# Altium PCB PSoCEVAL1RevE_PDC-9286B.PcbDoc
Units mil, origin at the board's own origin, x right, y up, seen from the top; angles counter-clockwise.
Board outline 3000 x 4000 mil, 2 copper layers (Top Layer, Bottom Layer); 58 components, 63 nets, 401 pads, 21 vias.
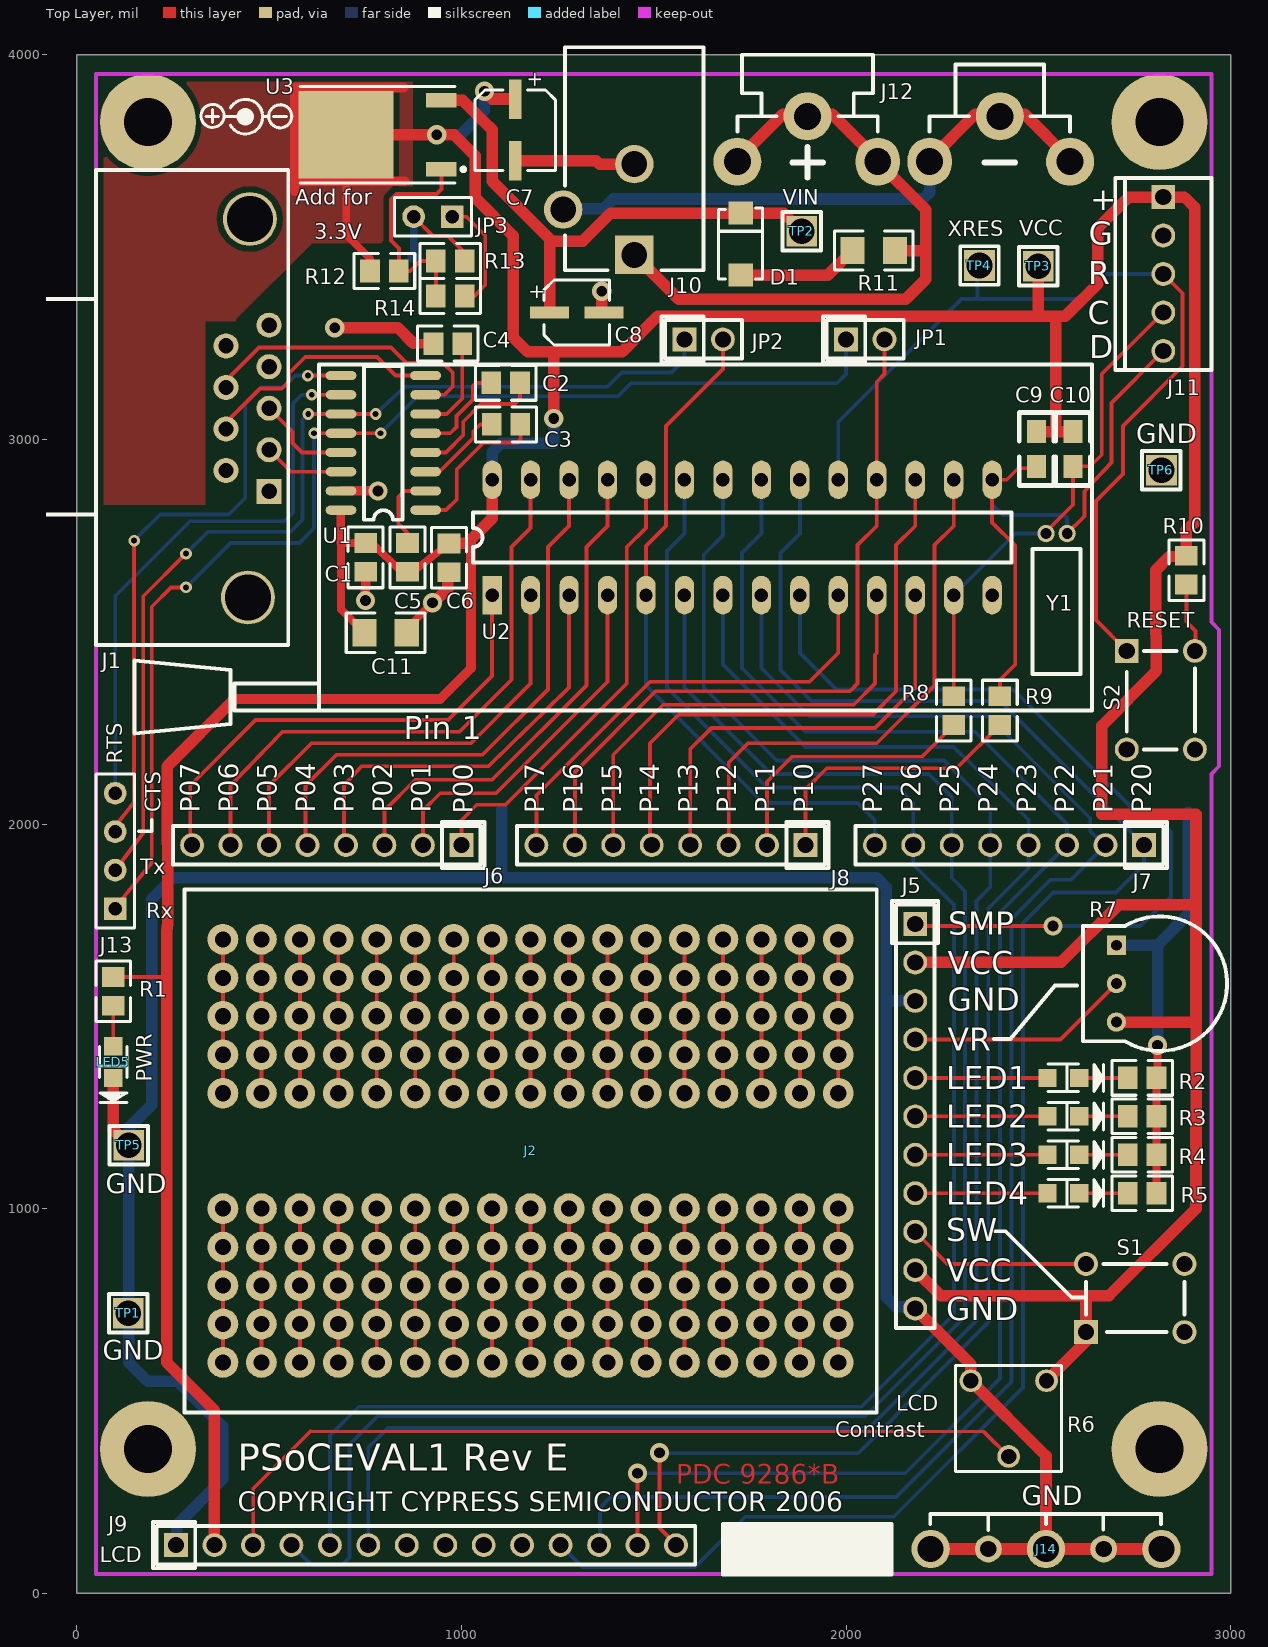
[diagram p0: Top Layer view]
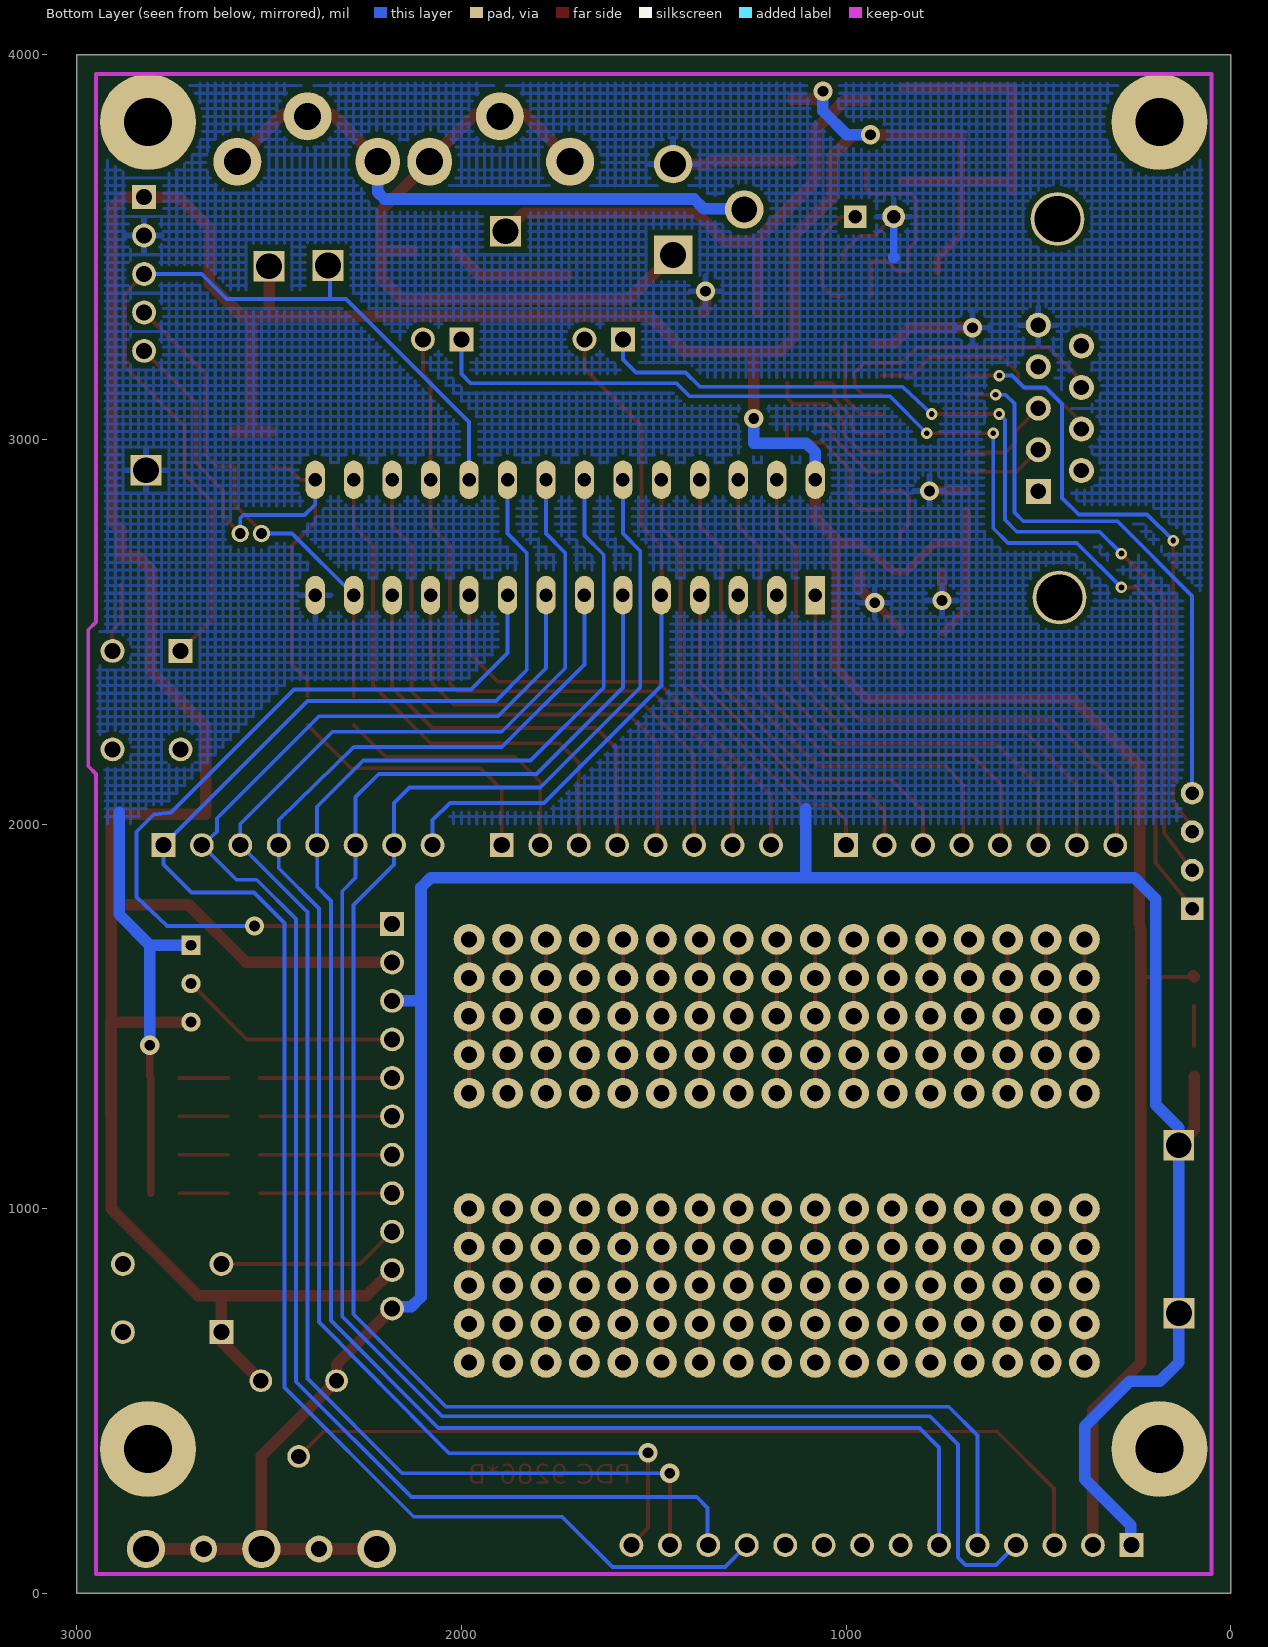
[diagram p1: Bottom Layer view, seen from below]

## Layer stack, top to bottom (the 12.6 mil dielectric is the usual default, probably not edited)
Top Layer: signal copper 1.4
Dielectric: dielectric 12.6, FR-4, Dk 4.8
Bottom Layer: signal copper 1.4

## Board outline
0,0 3000,0 3000,4000 0,4000

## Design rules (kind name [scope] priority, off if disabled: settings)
Clearance Clearance_1 [All vs InPoly] p1: gap=15
Clearance [All] p2: gap=8
ComponentClearance [All] p1: gap=10 collisioncheckmode=0 verticalgap=10
HoleSize [All] p1: absolutevalues=TRUE maxlimit=150 minlimit=15 maxpercent=80.000 minpercent=20.000
PolygonConnect [All] p1: connectstyle=Relief reliefconductorwidth=15 reliefentries=4 polygonreliefangle="90 Angle"
RoutingVias [All] p1: holewidth=25 width=40 viastyle="Through Hole" minholewidth=28 minwidth=50 maxholewidth=28 maxwidth=50
SolderMaskExpansion [All] p1: expansion=4
TestPointUsage [All] p1: valid=0 allowmultiple=FALSE
Testpoint [All] p1: side=15 testpointundercomponent=TRUE minsize=40 maxsize=100 preferedsize=60 minholesize=0 maxholesize=40 preferedholesize=32 testpointgrid=1 style=1023 order=0-112345678
Width [InNetClass('Power')] p1: maxlimit=100 minlimit=8 preferedwidth=10
17 further rules are at their usual default settings.

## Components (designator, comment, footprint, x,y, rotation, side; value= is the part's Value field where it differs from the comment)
C1 "" 0805#1 751,2693 r270 top
C2 "" 0805#1 1115,3147 r180 top
C3 "" 0805#1 1116,3039 r180 top
C4 "" 0805#1 965,3249 r0 top
C5 "" 0805#1 860,2693 r270 top
C6 "" 0805#1 968,2692 r270 top
C7 "" CAP_Nich_WT5.0 1140,3804 r270 top
C8 "" CAP_Nich_WT4-4.5 1300,3330 r0 top
C9 "DNP" 0805#2 2495,2930 r90 top
C10 "DNP" 0805#2 2590,2930 r90 top
C11 "10u" 1206 803,2497 r0 top
D1 "" SMA-A 1726,3427 r270 top
J1 "" DB9F 500,2865 r90 top
J2 "" BBOARD_1.8X1.4 1980,1700 r180 top
J5 "" HDR11X1 2180,1740 r270 top
J6 "" HDR8X1 1000,1945 r180 top
J7 "" HDR8X1 2775,1945 r180 top
J8 "" HDR8X1 1895,1945 r180 top
J9 "" HDR14X1 258,125 r0 top
J10 "" PWRCON 1450,3480 r90 top
J11 "" ISPCON 2825,3630 r270 top
J12 "" 9VBAT 1900,3840 r0 top
J13 "" HDR1X4 100,1780 r90 top
J14 "DNP" HDR5X1-GND 2820,115 r180 top
JP1 "DNP" HDR2x1 2000,3260 r0 top
JP2 "DNP" HDR2x1 1580,3260 r0 top
JP3 "" HDR1X2 976,3579 r180 top
LED1 "" LED0805 2565,1340 r0 top
LED2 "" LED0805 2565,1240 r0 top
LED3 "" LED0805 2565,1140 r0 top
LED4 "" LED0805 2565,1040 r0 top
LED5 "" LED0805 95,1381 r270 top
R1 "" R2012-0805 95,1565 r90 top
R2 "" R2012-0805 2770,1340 r180 top
R3 "" R2012-0805 2770,1240 r180 top
R4 "" R2012-0805 2770,1140 r180 top
R5 "" R2012-0805 2770,1040 r180 top
R6 "" POT_EVND8A 2423,454 r180 top
R7 "" POT-3352T 2703,1685 r270 top
R8 "" R2012-0805 2280,2295 r90 top
R9 "" R2012-0805 2400,2295 r90 top
R10 "" R2012-0805 2885,2660 r90 top
R11 "" 1206 2072,3491 r180 top
R12 "" R2012-0805 800,3438 r180 top
R13 "" R2012-0805 971,3464 r180 top
R14 "" R2012-0805 971,3373 r180 top
S1 "" STDSW 2624,679 r0 top
S2 "" STDSW 2730,2450 r270 top
TP1 "" TP64 134,728 r0 top
TP2 "DNP" TP64 1885,3541 r90 top
TP3 "DNP" TP64 2500,3450 r90 top
TP4 "DNP" TP64 2347,3452 r90 top
TP5 "" TP64 135,1165 r0 top
TP6 "" TP64 2820,2920 r90 top
U1 "" SO-16 907,2816 r180 top
U2 "" DIP-28-ZIF 1080,2595 r90 top
U3 "ADJ Vreg" KTP02 824,3792 r90 top
Y1 "DNP" XTAL32K 2525,2755 r90 top

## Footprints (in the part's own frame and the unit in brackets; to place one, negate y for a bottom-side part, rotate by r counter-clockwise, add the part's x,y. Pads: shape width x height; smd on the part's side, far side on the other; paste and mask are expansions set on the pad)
9VBAT [mil]
  round 125 hole 70: 1(-182.5,-118) 1(0,0) 2(500,0) 2(682.5,-118)
  oval 115x125 hole 70: 1(182.5,-118) 2(317.5,-118)
  silkscreen extent -182,-160 682,160
0805#1 [mm]
  rect 1.3x1.5 smd: 1(-0.95,0) 2(0.95,0)
  silkscreen extent -2,-1.15 2,1.15
0805#2 [mm]
  rect 1.524x1.27 smd: 1(0,0) 2(2.286,0)
  silkscreen extent -1.27,-1.14 3.56,1.14
1206 [mm]
  rect 1.6x1.8 smd: 1(-1.4,0) 2(1.4,0)
  silkscreen extent -2.6,-1.3 2.6,1.3
BBOARD_1.8X1.4 [mil] "28 tie point Breadboard  ( 3M 923273-I )"
  round 80 hole 42: ""(0,1100) ""(0,1000) ""(0,900) ""(0,800) ""(0,700) ""(0,400) ""(0,300) ""(0,200) ""(0,100) ""(0,0) ""(100,1000) ""(100,1100) ""(100,900) ""(100,800) ""(100,700) ""(100,300) ""(100,400) ""(100,200) ""(100,100) ""(100,0) ""(200,1100) ""(200,900) ""(200,1000) ""(200,700) ""(200,800) ""(200,400) ""(200,200) ""(200,300) ""(200,0) ""(200,100) ""(300,700) ""(300,800) ""(300,900) ""(300,1000) ""(300,1100) ""(300,300) ""(300,400) ""(300,0) ""(300,100) ""(300,200) ""(400,700) ""(400,800) ""(400,900) ""(400,1000) ""(400,1100) ""(400,300) ""(400,400) ""(400,0) ""(400,100) ""(400,200) ""(500,700) ""(500,800) ""(500,900) ""(500,1000) ""(500,1100) ""(500,300) ""(500,400) ""(500,0) ""(500,100) ""(500,200) ""(600,700) ""(600,800) ""(600,900) ""(600,1000) ""(600,1100) ""(600,0) ""(600,100) ""(600,200) ""(600,300) ""(600,400) ""(700,700) ""(700,800) ""(700,900) ""(700,1000) ""(700,1100) ""(700,0) ""(700,100) ""(700,200) ""(700,300) ""(700,400) ""(800,700) ""(800,800) ""(800,900) ""(800,1000) ""(800,1100) ""(800,0) ""(800,100) ""(800,200) ""(800,300) ""(800,400) ""(900,700) ""(900,800) ""(900,900) ""(900,1000) ""(900,1100) ""(900,0) ""(900,100) ""(900,200) ""(900,300) ""(900,400) ""(1000,700) ""(1000,800) ""(1000,900) ""(1000,1000) ""(1000,1100) ""(1000,0) ""(1000,100) ""(1000,200) ""(1000,300) ""(1000,400) ""(1100,1000) ""(1100,1100) ""(1100,0) ""(1100,100) ""(1100,200) ""(1100,300) ""(1100,400) ""(1100,700) ""(1100,800) ""(1100,900) ""(1200,1000) ""(1200,1100) ""(1200,0) ""(1200,100) ""(1200,200) ""(1200,300) ""(1200,400) ""(1200,700) ""(1200,800) ""(1200,900) ""(1300,1000) ""(1300,1100) ""(1300,0) ""(1300,100) ""(1300,200) ""(1300,300) ""(1300,400) ""(1300,700) ""(1300,800) ""(1300,900) ""(1400,1000) ""(1400,1100) ""(1400,0) ""(1400,100) ""(1400,200) ""(1400,300) ""(1400,400) ""(1400,700) ""(1400,800) ""(1400,900) ""(1500,1000) ""(1500,1100) ""(1500,0) ""(1500,100) ""(1500,200) ""(1500,300) ""(1500,400) ""(1500,700) ""(1500,800) ""(1500,900) ""(1600,1000) ""(1600,1100) ""(1600,0) ""(1600,100) ""(1600,200) ""(1600,300) ""(1600,400) ""(1600,700) ""(1600,800) ""(1600,900)
  Top Layer lines w10: 1600,1100 1600,700 ; 1600,400 1600,0 ; 1500,1100 1500,700 ; 1500,400 1500,0 ; 1400,1100 1400,700 ; 1400,400 1400,0 ; 1300,1100 1300,700 ; 1300,400 1300,0 ; 1200,1100 1200,700 ; 1200,400 1200,0 ; 1100,1100 1100,700 ; 1100,400 1100,0 ; 1000,1100 1000,700 ; 1000,400 1000,0 ; 900,1100 900,700 ; 900,400 900,0 ; 800,1100 800,700 ; 800,400 800,0 ; 700,1100 700,700 ; 700,400 700,0 ; 600,1100 600,700 ; 600,400 600,0 ; 500,1100 500,700 ; 500,400 500,0 ; 400,1100 400,700 ; 400,400 400,0 ; 300,1100 300,700 ; 300,400 300,0 ; 200,1100 200,700 ; 200,400 200,0 ; 100,1100 100,700 ; 100,400 100,0 ; 0,1100 0,700 ; 0,400 0,0
  silkscreen extent -100,-130 1700,1230
CAP_Nich_WT4-4.5 [mm]
  rect 2.6x0.8 smd: 1(-1.8,0) 2(1.8,0)
  silkscreen extent -2.15,-2.15 2.15,2.15
CAP_Nich_WT5.0 [mm]
  rect 2.6x0.8 smd: 1(-2.032,0) 2(2.032,0)
  silkscreen extent -2.65,-2.65 2.65,2.65
DB9F [mil]
  rect 65x65 hole 40: 1(0,0)
  round 65 hole 40: 2(108,0) 3(216,0) 4(324,0) 5(432,0) 6(54,112) 7(162,112) 8(270,112) 9(378,112)
  round 140 hole 120: ""(-276,55) ""(708,50)
  silkscreen extent -400,-50 835,600
DIP-28-ZIF [mil]
  rect 100x50 hole 35: 1(0,0)
  oval 100x50 hole 35: 2(0,-100) 3(0,-200) 4(0,-300) 5(0,-400) 6(0,-500) 7(0,-600) 8(0,-700) 9(0,-800) 10(0,-900) 11(0,-1000) 12(0,-1100) 13(0,-1200) 14(0,-1300) 15(300,-1300) 16(300,-1200) 17(300,-1100) 18(300,-1000) 19(300,-900) 20(300,-800) 21(300,-700) 22(300,-600) 23(300,-500) 24(300,-400) 25(300,-300) 26(300,-200) 27(300,-100) 28(300,0)
  silkscreen extent -360,-1560 600,930
HDR1X2 [mm] "Connector; Header; 2 Position"
  rect 1.5x1.5 hole 0.9: 1(0,0)
  round 1.5 hole 0.9: 2(2.54,0)
  silkscreen extent -1.27,-1.27 3.81,1.27
HDR1X4 [mm] "Connector; Header; 4 Position"
  rect 1.5x1.5 hole 0.889: 1(0,0)
  round 1.5 hole 0.889: 2(2.54,0) 3(5.08,0) 4(7.62,0)
  silkscreen extent -1.27,-1.27 8.89,1.27
HDR2x1 [mil]
  rect 62x62 hole 42: 1(0,0)
  round 62 hole 42: 2(100,0)
  silkscreen extent -60,-60 150,60
HDR5X1-GND [mil]
  round 100 hole 67: 1(0,0) 3(300,0) 5(600,0)
  round 70 hole 42: 2(150,0) 4(450,0)
HDR8X1 [mil]
  rect 62x62 hole 42: 1(0.12,-0.12)
  round 62 hole 42: 2(100.12,-0.12) 3(200.12,-0.12) 4(300.12,-0.12) 5(400.12,-0.12) 6(500.12,-0.12) 7(600.12,-0.12) 8(700.12,-0.12)
  silkscreen extent -60,-60 750,60
HDR11X1 [mil]
  rect 62x62 hole 42: 1(0,0)
  round 62 hole 42: 2(100,0) 3(200,0) 4(300,0) 5(400,0) 6(500,0) 7(600,0) 8(700,0) 9(800,0) 10(900,0) 11(1000,0)
  silkscreen extent -60,-60 1050,60
HDR14X1 [mil]
  rect 62x62 hole 42: 1(0,0)
  round 62 hole 42: 2(100,0) 3(200,0) 4(300,0) 5(400,0) 6(500,0) 7(600,0) 8(700,0) 9(800,0) 10(900,0) 11(1000,0) 12(1100,0) 13(1200,0) 14(1300,0)
  silkscreen extent -60,-60 1350,60
ISPCON [mil]
  rect 62x62 hole 42: 1(0,0)
  round 62 hole 42: 2(100,0) 3(200,0) 4(300,0) 5(400,0)
  silkscreen extent -50,-125 450,125
KTP02 [mm] "PowerFLEX (D-PAK/TO-252-AA); 3 Leads (1 Cropped); Body 9.7 (inc. leads) x 6.2 mm (LxW max)"
  rect 0.95x2 smd: 1(-2.285,-3.15) 3(2.285,-3.15)
  rect 5.8x6.3 smd: 4(0,3.15)
  silkscreen extent -3.2,-4.72 3.2,6.2
LED0805 [mm]
  rect 1.2x1.2 smd: A(-1.05,0) K(1.05,0)
  silkscreen extent -1.02,-0.9 2.67,0.9
POT-3352T [mil]
  rect 50x50 hole 28: 1(0,0)
  round 50 hole 28: 2(200,0) 3(100,0)
  silkscreen extent -75,-87 275,288
POT_EVND8A [mm]
  round 1.5 hole 1.016: 1(-2.5,-2.5) 2(2.5,-2.5) 3(0,2.5)
  silkscreen extent -3.5,-3.5 3.5,3.5
PWRCON [mil]
  rect 100x100 hole 67: 1(-0.33,0.33)
  round 100 hole 67: 2(235.67,0.33) 3(117.67,185.33)
  silkscreen extent -40,-180 540,180
R2012-0805 [mm]
  rect 1.3x1.5 smd: 1(-0.95,0) 2(0.95,0)
  silkscreen extent -2,-1.15 2,1.15
SMA-A [mm]
  rect 1.52x1.63 smd: 1(0,0) 2(-4.1,0)
  silkscreen extent -4.44,-1.45 0.25,1.45
SO-16 [mil]
  oval 80x24 smd: 1(0,0) 2(0,-50) 3(0,-100) 4(0,-150) 5(0,-200) 6(0,-250) 7(0,-300) 8(0,-350) 9(220,-350) 10(220,-300) 11(220,-250) 12(220,-200) 13(220,-150) 14(220,-100) 15(220,-50) 16(220,0)
  silkscreen extent 60,-375 160,25
STDSW [mil]
  rect 62x62 hole 42: 1(0,0)
  round 62 hole 42: 2(0,177) ""(256,0) ""(256,177)
  silkscreen extent 0,0 256,177
TP64 [mil]
  rect 80x80 hole 67: 1(0,0)
  silkscreen extent -50,-50 50,50
XTAL32K [mil]
  round 45 hole 28: 1(0,5) 2(0,-50)
  silkscreen extent -365,-85 -40,40

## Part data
C1 C2 C3 C4 C5 C7 C8 C11: library part CAPACITOR, "Capacitor"
C6 C9 C10: library part CAP, "Capacitor"
D1: library part "DIODE SCHOTTKY", "Schottky Diode"
J1: library part DB9, "Female DB-9"
J2: library part BREADBOARD, "3M solderless breadboard super strip"
J5: library part MHDR1X11, "Header, 11-Pin"
J6 J7 J8: library part CON8, "8-Pin Header, Female"
J9: library part LCD_MODULE, "14-Pin header, Female"
J10: library part PWRCON, "Power connector"
J11: library part CON5, "ISSP connector"
J12: library part BAT-9V-CONN, "9-Volt batter connector"
J13: library part "Header 4", "Header, 4-Pin"
J14: library part "Header 5", "Ground conn."
JP1 JP2 JP3: library part "Header 2", "Header, 2-Pin, Male"
LED1 LED2 LED3 LED4: library part LED
LED5: library part LED, "Red LED"
R1 R2 R3 R4 R5 R8 R9 R10 R11 R12 R13 R14: library part RES1, "Resistor, SMT"
R6 R7: library part POT1, "Potentiometer"
S1 S2: library part SPST, "Swtich, SPST"
TP1 TP2 TP3 TP4 TP5 TP6: library part TP, "Simple Test point"
U1: library part MAX232, "RS-232 tranceiver (1.0uF Caps)"
U2: library part CYMICRO_26443A, "CMS 27443, w/ socket"
U3: library part LM317MKTPR, "Adjustable Voltage Regulator"
Y1: library part CRYSTAL, "Crystal"

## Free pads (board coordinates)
  round 50 on Drill Drawing mask+12.01: 0(5550,4915) 0(5550,5215) 0(5550,5815) 0(5550,6265) 0(5550,6565) 0(5550,6865) 0(5550,7165) 0(5550,8265) 0(5800,7465) 0(5800,7765) 0(5800,8065)
  round 250 hole 125 paste+5: ""(185,375) ""(185,3825) ""(2815,375) ""(2815,3825)

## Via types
v1: diameter 30, hole 15, Top Layer to Bottom Layer, tented both sides, 9 vias
v2: diameter 50, hole 28, Top Layer to Bottom Layer, tented both sides, 8 vias
v3: diameter 50, hole 28, Top Layer to Bottom Layer, 4 vias

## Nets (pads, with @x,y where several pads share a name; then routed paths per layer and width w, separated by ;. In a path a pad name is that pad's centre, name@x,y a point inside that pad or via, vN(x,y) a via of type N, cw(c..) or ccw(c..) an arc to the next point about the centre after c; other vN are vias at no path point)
CTS: J13.3 U1.9 | length 1631.2
  Top Layer w10: J13.3 100,1994 149,2056 v1(149,2737) ; v1(601,3166) U1.9
  Bottom Layer w10: v1@150,2738 217,2805 395,2805 438,2848 438,3092 481,3135 537,3135 568,3166 v1(601,3166)
GND: C1.2 C4.1 C6.2 C7.2 C8.2 C11.2 J1.5 J5.3 J5.11 J9.1 J10.2 J11.2 J14.1 J14.2 J14.3 J14.4 J14.5 JP3.2 LED5.K R2.1 R3.1 R4.1 R5.1 R6.2 R7.1 R13.1 TP1.1 TP5.1 TP6.1 U1.15 U2.14 | length 9276.5
  Top Layer w10: 875,3249 875,3250 ; JP3.2 926,3529 965,3529 1008.4,3485.6 R13.1 ; C6.2@963,2649.6 C6.2
  Top Layer w20: C11.2 858.12,2508.12 v2(925,2575) ; R5.1 R4.1 R3.1 R2.1 2810,1342.6 v3(2810,1425)
  Top Layer w25: U1.15 v2(783,2866) ; v2(750.53,2581) C1.2 ; 875,3249 C4.1
  Top Layer w30: LED5.K@95,1343.66 LED5.K 95,1205 TP5.1 ; v3(671,3290) 835,3290 875,3250 ; v2(925,2575) 965,2610 C6.2@963,2649.6 ; C7.2@1140,3725 1350,3725 1360,3715 1449,3715 J10.2 J10.2@1450,3716 ; v2(1365,3385) 1365,3335.87 C8.2 ; J5.11 2324.57,595.43 R6.2 2520,357 J14.3 ; J14.5 J14.4 J14.3 ; 2600,116 2601,115 ; J14.1 J14.2 2601,115 ; J14.3 2601,115
  Bottom Layer w10: 875,3472 876,3473
  Bottom Layer w20: 876,3473 JP3.2
  Bottom Layer w30: J9.1 260,127 260,177 379,296 379,434 262,551 184,551 135,600 135,728 TP5.1 135,1210 195,1270 195,1805 250,1860 2080,1860 2105,1835 2105,770 2130,745 2175,745 J5.11 ; 874.99,3473.89 876,3473.89 ; 1105,1860 1105,2040 ; 2105,1540 J5.3 ; R7.1 2810,1685 ; v3(2810,1425) 2810,1685 ; J11.2@2820,3525 J11.2 ; 2890,2030 2890,1765 2810,1685
NetC2_1: C2.1 U1.4 | length 364.7
  Top Layer w10: U1.4 960,2966 1005,3011 1005,3046 1051,3092 1138,3092 1152.4,3106.4 C2.1
NetC2_2: C2.2 U1.5 | length 262.4
  Top Layer w10: U1.5 971,3016 987,3032 987,3061 1030,3104 1030,3139 1038,3147 C2.2
NetC3_1: C3.1 U1.1 | length 407.7
  Top Layer w10: U1.1 960,2816 988,2844 988,2922 1058,2992 1146,2992 1153.4,2999.4 C3.1
NetC3_2: C3.2 U1.3 | length 232.5
  Top Layer w10: U1.3 943,2916 1031,3004 1031,3021 1049,3039 C3.2
NetC4_2: C4.2 U1.6 | length 254.7
  Top Layer w10: U1.6 962,3066 1002.4,3106.4 C4.2
NetC5_1: C5.1 U1.2 | length 207.8
  Top Layer w10: C5.1 860,2757 836,2781 836,2851 851,2866 U1.2
NetC8_1: C8.1 D1.2 TP2.1 U3.3 | length 1406.4
  Top Layer w10: 1230,3515 1230,3521
  Top Layer w30: U3.3 1003.04,3881.96 1059,3826 1080,3805 1080,3671 1230,3521 ; C8.1 1230,3330.87 1230,3515 1315,3515 1388.42,3588.42 D1.2 1837.58,3588.42 TP2.1
NetD1_1: D1.1 R11.2 | length 317.4
  Top Layer w30: D1.1 1952.88,3427 R11.2
NetJ1_2: J1.2 U1.14 | length 210.6
  Top Layer w10: J1.2 557,2916 U1.14
NetJ1_3: J1.3 U1.13 | length 251.6
  Top Layer w10: J1.3 561,3020 561,2991 586,2966 U1.13
NetJ1_7: J1.7 U1.8 | length 638
  Top Layer w10: J1.7 388,3044 476,3132 533,3132 552,3151 552,3172 595,3215 ; 596,3214 781,3214 829,3166 U1.8
NetJ1_8: J1.8 U1.7 | length 785.6
  Top Layer w10: J1.8 388,3153 474,3239 817,3239 857,3199 952,3199 977.4,3173.6 977.4,3137.4 956,3116 U1.7
NetJ5_4: J5.4 R7.3 | length 583.1
  Top Layer w10: J5.4 2558,1440 R7.3
NetJ5_5: J5.5 LED1.A | length 343.7
  Top Layer w10: J5.5 LED1.A
NetJ5_6: J5.6 LED2.A | length 343.7
  Top Layer w10: J5.6 LED2.A
NetJ5_7: J5.7 LED3.A | length 343.7
  Top Layer w10: J5.7 LED3.A
NetJ5_8: J5.8 LED4.A | length 343.7
  Top Layer w10: J5.8 LED4.A
NetJ5_9: J5.9 S1.2 | length 478.8
  Top Layer w10: J5.9 2264,856 S1.2
NetJ9_3: J9.3 R6.3 | length 2200.1
  Top Layer w10: J9.3 459,126 459,272 608,421 2359,420.02 2359,419.57 R6.3
NetJ10_1: J10.1 J12.1 R11.1 | length 1727.9
  Top Layer w30: J10.1@1429.67,3479.67 J10.1@1430,3479.34 ; J10.1 1565.34,3364 2155,3364 2207,3416 2207,3490 ; J12.1@1717.5,3727 1835.5,3845 1900,3845 1964.5,3845 J12.1@2082.5,3727 ; J12.1@2082.5,3722 2207,3597.5 2207,3490 ; R11.1 2128.12,3490 2207,3490
NetJ10_3: J10.3 J12.2 | length 1514.2
  Top Layer w30: J12.2@2217.5,3727 2335.5,3845 2400,3845 2464.5,3845 2582.5,3727 J12.2@2582.5,3727.5
  Bottom Layer w10: J10.3 J10.3@1267,3600
  Bottom Layer w30: J10.3@1267,3600 1370,3600 1395,3625 2200,3625 2217.5,3642.5 J12.2@2217.5,3722
NetJP3_1: JP3.1 R14.1 | length 300.5
  Top Layer w10: JP3.1 1013,3579 1062,3530 1062,3401 1034,3373 R14.1
NetLED1_K: LED1.K R2.2 | length 126.3
  Top Layer w10: LED1.K R2.2
NetLED2_K: LED2.K R3.2 | length 126.3
  Top Layer w10: LED2.K R3.2
NetLED3_K: LED3.K R4.2 | length 126.3
  Top Layer w10: LED3.K R4.2
NetLED4_K: LED4.K R5.2 | length 126.3
  Top Layer w10: LED4.K R5.2
NetLED5_A: LED5.A R1.1 | length 105.3
  Top Layer w10: LED5.A R1.1
NetR10_1: R10.1 S2.2 | length 182.6
  Top Layer w10: R10.1 2885,2526 2909,2502 S2.2
NetR12_1: R12.1 R13.2 R14.2 U3.1 | length 585.6
  Top Layer w10: R14.2 R13.2 893,3464 867,3438 R12.1 837.4,3496.6 817,3517 817,3624 831,3638 935,3638 948.02,3651.02 U3.1
P00: J6.1 U2.24 | length 1192.7
  Top Layer w10: J6.1 999.88,2009.88 1040,2050 1115,2050 1430,2365 1430,2720 1480,2770 U2.24
P01: J6.2 U2.4 | length 933.7
  Top Layer w10: J6.2 900,1945.24 900,2035 945,2080 1090,2080 1380,2370 1380,2445 U2.4
P02: J6.3 U2.25 | length 1307.3
  Top Layer w10: J6.3 800,2035 880,2115 1080,2115 1325,2360 1325,2720 1380,2775 U2.25
P03: J6.4 U2.3 | length 1087.6
  Top Layer w10: J6.4 695,1950 695,2100 740,2150 1070,2150 1280,2355 1280,2445 U2.3
P04: J6.5 U2.26 | length 1458.2
  Top Layer w10: J6.5 595,1950 595,2100 675,2180 1055,2180 1225,2350 1225,2720 1280,2775 U2.26
P05: J6.6 U2.2 | length 1174.7
  Top Layer w10: J6.6 500,1945.24 500,2100 610,2210 1025,2210 1180,2365 1180,2445 U2.2
P06: J6.7 U2.27 | length 1541
  Top Layer w10: J6.7 400,2100 535,2240 995,2240 1130,2375 1130,2720 1180,2770 U2.27
P07: J6.8 U2.1 | length 1270
  Top Layer w10: J6.8 295,1950 295,2100 465,2270 965,2270 1080,2385 U2.1
P10: J8.1 R9.1 | length 719.4
  Top Layer w10: J8.1 1894.88,2089.88 1950,2145 2287.4,2145 R9.1
P10A: C9.1 J11.5 R9.2 U2.15 Y1.2 | length 1625
  Top Layer w10: R9.2 2400,2375 2440,2415 2440,2724 2380,2784 U2.15 2418,2895 2448,2925 2490,2925 C9.1 ; Y1.2 2620,2800 2620,2865 2690,2940 2690,3095 J11.5
  Bottom Layer w10: U2.15 2380,2831 2408,2803 2566.01,2803 ; 2566.5,2803.5 2566.01,2803 ; Y1.2 2575,2795 2566.01,2803
P11: J8.2 R8.1 | length 711.1
  Top Layer w10: J8.2 1794.88,2109.88 1860,2175 2197.4,2175 R8.1
P11A: C10.1 J11.4 R8.2 U2.13 Y1.1 | length 1396.5
  Top Layer w10: R8.2 2280,2445 U2.13 ; Y1.1 2520,2760 2590.15,2830.15 ; J11.4 2665,3170 2665,2960 2635,2930 C10.1 ; C10.1 2590.15,2929.85 2590.15,2830.15 ; C10.1 2590.15,2830.15
  Bottom Layer w10: U2.13 2440,2755 Y1.1
P12: J8.3 U2.16 | length 1388.5
  Top Layer w10: J8.3 1695,1945.24 1695,2160 1745,2210 2080,2210 2230,2360 2230,2725 2280,2775 U2.16
P13: J8.4 U2.12 | length 1141.2
  Top Layer w10: J8.4 1595,1945.24 1595,2195 1650,2250 2075,2250 2180,2355 2180,2445 U2.12
P14: J8.5 U2.17 | length 1533.5
  Top Layer w10: J8.5 1490,1950 1490,2210 1565,2285 2070,2285 2130,2345 2130,2725 2180,2775 U2.17
P15: J8.6 U2.11 | length 1223.6
  Top Layer w10: J8.6 1394.88,2179.88 1525,2310 2020,2310 2075,2365 2075,2440 2080,2445 U2.11
P16: J8.7 JP1.2 U2.18 | length 1944.2
  Top Layer w10: J8.7 1295,1945.24 1295,2135 1505,2345 2010,2345 2030,2365 2030,2725 2080,2775 U2.18 2080,3045 2080,3150 2100,3170 JP1.2
P17: J8.8 U2.10 | length 1218.2
  Top Layer w10: J8.8 1194.88,2074.88 1490,2370 1905,2370 1980,2445 U2.10
P20: J7.1 J9.11 U2.20 | length 4704
  Bottom Layer w10: J9.11 1315,68 1607,68 1738,199 2124,199 2460,535 2460,1742.58 2539,1821.58 2701.58,1821.58 2774.88,1894.88 J7.1 ; U2.20 1880,2755 1830,2705 1830,2400 1910,2320 2400,2320 J7.1 ; J7.1@2775,1945.24 J7.1
P21: J7.2 J9.12 U2.8 | length 4125.7
  Bottom Layer w10: J9.12 1360,127 1360,222 1388,250 2130,250 2430,550 2430,1753 2532,1855 2584.76,1855 J7.2 2635,1980 2635,2015 2370,2280 1905,2280 1780,2405 U2.8
P22: J7.3 J9.13 U2.21 | length 4269.7
  Top Layer w10: J9.13 v2(1458,312)
  Bottom Layer w10: v2(1458,312) 2154,312 2400,558 2400,1772 2401.76,1772 J7.3 ; U2.21 1780,2755 1730,2705 1730,2405 1895,2240 2335,2240 2575,2000 J7.3@2575,1945.24
P23: J7.4 J9.14 U2.7 | length 3744
  Top Layer w10: v2(1515,365) 1515,170 J9.14
  Bottom Layer w10: v2(1515,365) 2032,364 2051,383 2370.05,705.05 ; U2.7 1680,2415 1895,2200 2280,2200 2475,2010 J7.4@2475,1945.24 ; 2370,705.11 2370,1780 2474.88,1884.88 J7.4
P24: J7.5 J9.6 U2.22 | length 4756.5
  Bottom Layer w10: J9.6 758,379 809,430 2060,430 2339.12,709.12 2339.12,1800 2374.88,1835.76 J7.5 ; U2.22 1680,2750 1630,2700 1630,2355 1820,2165 2255,2165 2375,2045 J7.5@2375,1945.24
P25: J7.6 J9.4 U2.6 | length 4631.1
  Bottom Layer w10: J9.4 610,73 689,73 709,93 709,387 782,460 2050,460 2309.76,719.76 2309.76,1825.24 2274.88,1860.12 J7.6 2274.88,2070.12 2215,2130 1805,2130 1580,2355 U2.6
P26: J7.7 J9.5 U2.23 | length 4734.5
  Bottom Layer w10: J9.5 658,410 733,485 2040,485 2280.49,725.49 2280.49,1789.51 2175,1895 2175,1945.12 J7.7@2175,1945.24 ; U2.23 1580,2755 1535,2710 1535,2355 1795,2095 2135,2095 2175,2055 J7.7@2175,1945.24 ; J7.7 J7.7@2175,1945.24
P27: J7.8 JP2.2 U2.5 | length 1787.8
  Top Layer w10: U2.5 1480,2723 1532,2775 1532,3035 1680,3183 JP2.2
  Bottom Layer w10: U2.5 1480,2360 1785,2055 2030,2055 2074.88,2010.12 J7.8 J7.8@2075,1945.24
RTS: J13.4 U1.10 | length 1482.4
  Top Layer w10: v1(611,3116) U1.10
  Bottom Layer w10: J13.4 100,2593 294,2787 539,2787 562,2810 562,3093 585,3116 v1(611,3116)
RX: J13.1 JP1.1 U1.12 | length 3116.8
  Top Layer w10: J13.1@93,1775 98.28,1781.42 195,1899 195,2565 245,2615 v1(284,2615) ; v1(617,3016) v1(790,3016)
  Bottom Layer w10: v1(284,2615) 400,2731 579,2731 617,2769 v1(617,3016) ; v1(790,3016) 886,3112 1407,3112 1441,3146 1976,3146 2000,3170 JP1.1
SMP: J5.1 U2.9 | length 2172.5
  Top Layer w10: J5.1 2185,1735 v2(2538,1735)
  Bottom Layer w10: U2.9 1880,2445 1975,2350 2435,2350 2755,2030 2800,2025 2845,1980 2845,1810 2765,1735 v2(2538,1735)
TX: J13.2 JP2.1 U1.11 | length 2612
  Top Layer w10: J13.2 173,1977 173,2592 v1(284,2703) ; v1(602,3066) v1(777,3066)
  Bottom Layer w10: v1(284,2703) 341,2760 556,2760 587,2791 587,3051 v1(602,3066) ; v1@786.4,3069.4 783,3066 v1(777,3066) 854,3137 1380,3137 1417,3174 1546,3174 1580,3208 JP2.1
VCC: C1.1 C5.2 C6.1 C7.1 C9.2 C10.2 C11.1 J5.2 J5.10 J9.2 J11.1 R1.2 R6.1 R7.2 R10.2 R12.2 S1.1 TP3.1 U1.16 U2.28 U3.4 | length 14993.3
  Top Layer w10: R1.2 233.6,1602.4 234,1602 ; U3.4 U3.4@700.4,3791.58 ; 852,3671 853,3672
  Top Layer w20: U3.4@700.4,3791.58 700.4,3531.6 762.6,3469.4 R12.2 ; C11.1 687,2557.88 687,2585.47 U1.16 685,2805 685,2730 717.6,2730.4 768.6,2730.4 843.4,2655.6 872.6,2655.6 C6.1
  Top Layer w25: 410,2325 770,2325 945,2325 1025,2405 1025,2744 ; 567,3645 567,3915 850,3915 ; 567,3671 852,3671
  Top Layer w30: R1.2 R1.2@97.6,1605 ; J9.2 358,476 234,600 234,1722 237,1741 235,2150 410,2325 ; U3.4 981,3792 1036,3737 1036,3628 1135,3529 1135,3265 1172,3228 1418,3228 1510,3320 2570,3320 2655,3405 2655,3550 2735,3630 J11.1 2880,3630 2907,3603 2907,2784 2885,2765 R10.2 2840,2695 2805,2660 2805,2585 2807,2398 2665,2255 2665,2025 2910,2025 2910,1485 R7.2 ; C6.1 1014.4,2729.4 1080,2795 U2.28 U2.28@1077.6,2897.4 ; v2(1060,3905) 1080,3885 C7.1@1140,3885 ; v3@1240,3048 1240,3228 ; J5.10 2246,774 2685,774 ; J5.2 2560,1641 2709,1790 2910,1790 ; C9.2 C10.2 ; 2500,3320 TP3.1 ; R6.1 2624,655 S1.1 2624,774 ; 2545,3020 2545,3320 ; 2684,774 2910,1000 2911,1484
  Bottom Layer w30: v3(936,3792) 998,3792 1060,3854 v2(1060,3905) ; U2.28 1080,2967 1103,2990 1240,2990 v3@1240,3052.95
  other v3: 1240,3054
XRES: J11.3 S2.1 TP4.1 U2.19 | length 2370.6
  Top Layer w10: S2.1 2650,2530 2650,2840 2720,2910 2720,3035 2875,3190 2875,3380 J11.3
  Bottom Layer w10: U2.19 1980,3045 2300,3365 2610,3365 2675,3430 J11.3 ; 2342,3365 2342,3447 TP4.1
pads on no net: J1. J1.1 J1.4 J1.6 J1.9 J2. J9.7 J9.8 J9.9 J9.10 S1. S2.

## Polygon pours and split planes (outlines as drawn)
VCC on Top Layer "Top Layer-VCC" (solid, remove dead copper, pour order 1000): 53,3954 873,3954 873,3510 609,3510 609,3508 413,3312 413,3307 334,3307 334,2830 49,2830 49,3954
GND on Bottom Layer "Bottom Layer-GND" (hatched 90Degree grid 20 track 8, remove dead copper, pour order 1001): 44,3956 2947,3956 2947,2000 49,2000 49,3956
no net on Top Overlay (hatched Horizontal grid 8 track 10, remove dead copper): 1680,180 2119,180 2119,49 1680,49

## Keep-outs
Keep-Out Layer:
  lines w10: 50,50 2950,50 2950,2130 2970,2150 2970,2505 2950,2525 2950,3950 50,3950 50,50

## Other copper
Top Layer:
  text "TOP COPPER (.GTL)" at 5478,1246 h80
  text "PDC 9286*B" at 1558,285 h50
Bottom Layer:
  text "BOTTOM COPPER (.GBL)" at 5473,1081 h80

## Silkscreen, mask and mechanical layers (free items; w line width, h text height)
Top Overlay:
  circle w25: c438.11,3839 r10
  circle w8: c353,3841 r30
  circle w8: c529,3840 r30
  lines w8: 336,3840 369,3840 ; 353,3824 353,3857 ; 384,3839 421,3839 ; 399.45,3816.7 ccw(c438.42,3839.2) 399.45,3861.7 ; 483,3839 498,3839 ; 512,3839 545,3839
  lines w10: 162,1981 195,1981 195,2010 ; 2219,180 2219,206 2819,206 2819,180 ; 2370,164 2370,206 ; 2385,1441 2427,1441 ; 2387,941 2415,941 2587,769 2621,769 2624,766 ; 2428,1441 2543,1580 2601,1580 ; 2520,180 2520,206 ; 2669,165 2669,206
  text "Add for" at 568,3610 h40
  text "VIN" at 1836,3610 h40
  text "+" at 2635,3596 h60
  text "VCC" at 2450,3530 h40
  text "XRES" at 2264,3528 h40
  text "3.3V" at 618,3520 h40
  text "G" at 2631,3506 h60
  text "R" at 2630,3403 h60
  text "C" at 2629,3300 h60
  text "D" at 2632,3211 h60
  text "GND" at 2755,2990 h50
  text "RESET" at 2730,2510 h40
  text "Pin 1" at 850,2220 h60
  text "RTS" at 118,2157 h40 r90
  text "CTS" at 218,2030 h40 r90
  text "P07" at 320,2029 h50 r90
  text "P06" at 420,2029 h50 r90
  text "P05" at 520,2029 h50 r90
  text "P04" at 620,2029 h50 r90
  text "P03" at 720,2029 h50 r90
  text "P02" at 820,2029 h50 r90
  text "P01" at 920,2029 h50 r90
  text "P17" at 1215,2028 h50 r90
  text "P16" at 1315,2028 h50 r90
  text "P15" at 1415,2028 h50 r90
  text "P14" at 1515,2028 h50 r90
  text "P13" at 1615,2028 h50 r90
  text "P12" at 1715,2028 h50 r90
  text "P11" at 1815,2028 h50 r90
  text "P10" at 1915,2028 h50 r90
  text "P27" at 2094,2028 h50 r90
  text "P26" at 2194,2028 h50 r90
  text "P25" at 2294,2028 h50 r90
  text "P24" at 2394,2028 h50 r90
  text "P23" at 2494,2028 h50 r90
  text "P22" at 2594,2028 h50 r90
  text "P21" at 2694,2028 h50 r90
  text "P20" at 2794,2028 h50 r90
  text "P00" at 1030,2027 h50 r90
  text "Tx" at 165,1870 h40
  text "Rx" at 180,1755 h40
  text "SMP" at 2266,1712 h60
  text "VCC" at 2265,1610 h60
  text "TOP OVERLAY (.GTO)" at 5483,1546 h80
  text "GND" at 2265,1515 h60
  text "VR" at 2265,1410 h60
  text "PWR" at 195,1330 h40 r90
  text "GND" at 75,1040 h50
  text "SW" at 2260,915 h60
  text "VCC" at 2260,810 h60
  text "GND" at 2260,710 h60
  text "GND" at 68,607 h50
  text "LCD" at 2131,475 h40
  text "Contrast" at 1972,405 h40
  text "PSoCEVAL1 Rev E" at 418,319 h70
  text "GND" at 2457,229 h50
  text "COPYRIGHT CYPRESS SEMICONDUCTOR 2006" at 419,213 h50
  text "LCD" at 60,80 h40
Top Paste:
  text "TOP PASTE (.GTP)" at 5479,1741 h80
Top Solder:
  text "TOP SOLDERMASK (.GTS)" at 5478,1396 h80
Bottom Solder:
  text "BOTTOM SOLDERMASK (.GBS)" at 5473,931 h80
Mechanical 1:
  the board outline again, w10
Drill Drawing:
  lines w8: 8545,6610 8565,6630 ; 8570,6610 8590,6630
  lines w10: -563.11,8515 3486.89,8516.77 ; -88.11,8716.77 -85,4520 ; 485,4520 486.89,8716.77 ; 5422,-529 5422,571 cw(c5522,571) 5522,671 11072,671 cw(c11072,571) 11172,571 11172,-529 cw(c11072,-529) 11072,-629 5521.24,-628.98 cw(c5523,-528) 5422,-528 ; 5897,-479 5997,-479 ; 6497,-479 6597,-479 ; 6722,-379 5522,-379 ccw(c5522,-429) 5472,-429 5472,-529 ccw(c5522,-529) 5522,-579 6722,-577 ccw(c6722,-529) 6770,-529 ; 6722,-329 5522,-329 cw(c5522,-279) 5472,-279 5472,571 cw(c5522,571) 5522,621 6722,621 ; 6722,-327 ccw(c6722,-279) 6770,-279 ; 6723,-379 cw(c6723,-428) 6772,-428 ; 6723,621 cw(c6723,572) 6772,572 ; 6772,-529 6772,-429 ; 6772,-279 6772,571 ; 6871.13,-578.99 cw(c6872,-529) 6822,-529 6822,-429 cw(c6872,-429) 6872,-379 8547,-379 cw(c8547,-429) 8597,-429 8597,-529 ; 6871.13,-328.99 cw(c6872,-279) 6822,-279 6822,-54 cw(c6872,-54) 6872,-4 7622,-4 ; 6872,-579 8547,-579 ; 6872,-329 7622,-329 ; 7621.29,-4.03 cw(c7623,-53) 7672,-53 ; 7622,46 6872,46 cw(c6872,96) 6822,96 6822,321 cw(c6872,321) 6872,371 7622,371 ; 7623,-329 ccw(c7623,-280) 7672,-280 ; 7623,371 cw(c7623,322) 7672,322 ; 7624,46 ccw(c7624,94) 7672,94 ; 7672,-279 7672,-54 ; 7672,96 7672,321 ; 7722,-280 ccw(c7771,-280) 7771,-329 9373,-329 ccw(c9373,-280) 9421.99,-279.14 ; 7722,-279 7722,-154 cw(c7772,-154) 7772,-104 9372,-104 ; 7722,-5 ccw(c7771,-5) 7771,-54 ; 7722,-4 7722,321 cw(c7772,321) 7772,371 9822,371 cw(c9822,321) 9872,321 9872,-4 cw(c9822,-4) 9822.87,-54 ; 7772,-54 9822,-54 ; 8548.16,-579 ccw(c8549,-531) 8596.98,-529.32 ; 8696.13,-578.99 cw(c8697,-529) 8647,-529 8647,-429 cw(c8697,-429) 8697,-379 10372,-379 cw(c10372,-429) 10422,-429 10422,-529 ; 8697,-579 10372,-579 ; 9373,-104 cw(c9373,-153) 9422,-153 ; 9422,-279 9422,-154 ; 9472,-279 9472,-154 ; 9472,-278 ccw(c9523,-278) 9522.11,-328.99 ; 9472.07,-154.51 cw(c9520,-152) 9520,-104 ; 9522,-329 9822,-329 ccw(c9822,-279) 9872,-279 9872,-154 ; 9522,-104 9822,-104 ; 9823,-104 cw(c9823,-153) 9872,-153 ; 9922,-280 ccw(c9971,-280) 9971.86,-328.99 ; 9922,-279 9922,-154 cw(c9972,-154) 9972,-104 11072,-104 ; 9972,-329 11072,-329 ccw(c11072,-279) 11122,-279 11122,-179 ; 10373.16,-579 ccw(c10374,-531) 10421.98,-529.32 ; 10472,-530 ccw(c10521,-530) 10521.86,-578.99 ; 10472,-529 10472,-429 cw(c10522,-429) 10522,-379 11072,-379 cw(c11072,-429) 11122,-428.13 ; 10522,-579 11072,-579 ccw(c11072,-529) 11122,-529 11122,-429 ; 11071.29,620.97 cw(c11073,572) 11122,572 ; 11072,621 9972,621 ccw(c9972,571) 9922,571 9922,-4 ccw(c9972,-4) 9972,-54 11072,-54 ccw(c11072,-4) 11122,-4 11122,571 ; 11073,-104 cw(c11073,-153) 11122,-153 ; -563.11,4520 -563.11,8716.77 3486.89,8716.77 3486.89,4520 -563.11,4520 ; 0,0 3000,0 3000,4000 0,4000 0,0 ; 6822,471 ccw(c6872,471) 6872,421 9822,421 ccw(c9822,471) 9872,471 9872,571 ccw(c9822,571) 9822,621 6872,621 ccw(c6872,571) 6822,571 6822,471
  text "FABRICATION NOTES:" at 5500,8750 h150
  text "THROUGH HOLE" at 644.86,8741.62 h100
  text "MARK" at -430.14,8566.62 h80
  text "QTY" at 94.86,8566.62 h80
  text "DIAM" at 1094.86,8566.62 h80
  text "PLTD" at 2419.86,8566.62 h80
  text "1. RoHS COMPLIANT CERTIFICATION OR MATERIAL DECLARATION REQUIRED." at 5500,8525 h80
  text "2. MATERIAL:" at 5500,8375 h80
  text "UNLESS OTHERWISE SPECIFIED IN THE STACK VIEW:" at 5700,8225 h80
  text "A. NELCO 4000-11 OR IS420 OR EQUIVALENT. MATERIAL" at 5900,8025 h80
  text "MUST CONFORM TO UL94V-0." at 5900,7875 h80
  text "B. USE 1/2 oz. COPPER FOIL FOR EXTERNAL LAYERS, 1 oz" at 5900,7725 h80
  text "COPPER FOIL FOR INTERNAL LAYERS." at 5900,7575 h80
  text "C. OVERALL METAL THICKNESS .063 +/- 10%." at 5900,7425 h80
  text "3. DRILLING:" at 5500,7275 h80
  text "A. DIAMETERS IN DRILL TABLE ARE FINISHED HOLE SIZES" at 5750,7125 h80
  text "+/- .003 UNLESS SPECIFIED." at 5750,6975 h80
  text "B. TEARDROP ALLOWED ON ENTRY OF VIA ON EVERY TRACE LAYER." at 5750,6825 h80
  text "4. PLATING:" at 5500,6675 h80
  text "A. COPPER PLATING IN THRU-HOLES .001\" min." at 5750,6525 h80
  text "5. MARKINGS:" at 5500,6375 h80
  text "A. SILKSCREEN IN WHITE NON-CONDUCTIVE EPOXY INK ON" at 5750,6225 h80
  text "PRIMARY SIDE OF THE BOARD OR BOTH SIDES IF APPLICABLE." at 5750,6075 h80
  text "6. FINAL FABRICATION:" at 5500,5925 h80
  text "A. SOLDERMASK PRIMARY AND SECONDARY SIDE OF BOARD" at 5750,5775 h80
  text "USING LIQUID PHOTOIMAGABLE MASK OVER BARE" at 5750,5625 h80
  text "COPPER PER IPC-SM-840. SOLDERMASK COLOR **BLUE**." at 5750,5475 h80
  text "7. FINISH:" at 5500,5325 h80
  text "A. SHALL BE ELECTROLYTIC NICKEL/GOLD. ELECTROLESS" at 5750,5175 h80
  text "ELECTROLESS NICKEL/IMMERSION GOLD (ENIG)." at 5750,5025 h80
  text "B. NICKEL THICKNESS: 100-200 MICROINCHES/" at 5750,4875 h80
  text "GOLD THICKNESS 3-10 MICROINCHES." at 5750,4725 h80
  text ".LEGEND" at -255,4645 h80
  text "8. BOARDS SHALL BE PURCHASED FROM UL RECOGNIZED VENDORS" at 5500,4575 h80
  text "ONLY AND SHALL BE MARKED IN COPPER ON SECONDARY SIDE" at 5750,4425 h80
  text "OF BOARD WITH VENDORS UL IDENTIFICATION FLAMMABILITY" at 5750,4275 h80
  text "RATING (94V-0), DATE CODE (WWYY) AND RHoS COMPLIANT" at 5750,4125 h80
  text "SYMBOL." at 5750,3975 h80
  text "9. MANUFACTURED BOARD TO BE IN ACCORDANCE WITH" at 5500,3825 h80
  text "PERFORMANCE STANDARD IPC-6011/6012 CLASS 2. BOARD TO BE" at 5750,3675 h80
  text "INSPECTED PER IPC-600-A CLASS 2." at 5750,3525 h80
  text "10. MAXIMUM BOW OR TWIST SHALL NOT EXCEED 0.007 in/in." at 5500,3375 h80
  text "LAYER CONSTRUCTION - FILE IDENTIFICATION" at 5473,2112 h100
  text "DRILL AND TRIM(.GD1)" at 5479,1920 h80
  text "Cypress" at 8038,501 h80
  text "Cypress Semiconductor" at 9985,467 h60
  text "ALL DIM IN MILS" at 5656,418 h70
  text "10147 W. Emerald Street" at 9989,340 h50
  text "TITLE:" at 7759.5,283.5 h45
  text "ENGR:" at 6872,271 h45
  text "Boise" at 9990,236 h50
  text "Robin Randel" at 6851,178 h45
  text "PSoCEVAL1" at 8424,123 h70
  text "Idaho 83704" at 9998,117 h50
  text "(208) 489-9382" at 6907,96 h50
  text "SNF@CYPRESS.COM" at 9992,-4 h55
  text "DWN:" at 6847,-109 h45
  text "Brian Sherer" at 7037,-109 h50
  text "PART NO.:" at 7772,-191.5 h45
  text "REV:" at 9509.5,-191.5 h45
  text "DATE:" at 9972,-191.5 h45
  text "PDC-9286*B" at 8179,-238 h70
  text "31 OCT 06" at 10271,-246 h80
  text "(206) 853-8470" at 6922,-259 h50
  text "E" at 9665,-285 h120
  text "MATERIAL" at 5522,-454 h45
  text "FILE NAME:" at 6872,-469 h45
  text "LAYER:" at 8712,-469 h45
  text "GERBER:" at 10532,-469 h45
  text "SEE NOTES" at 6047,-504 h45

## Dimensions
0,0 to 185,375 on Mechanical 1
0,0 to 185,375 on Mechanical 1
0,0 to 3000,0 on Drill Drawing
0,0 to 0,4000 on Drill Drawing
